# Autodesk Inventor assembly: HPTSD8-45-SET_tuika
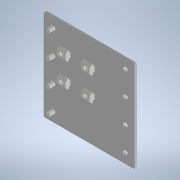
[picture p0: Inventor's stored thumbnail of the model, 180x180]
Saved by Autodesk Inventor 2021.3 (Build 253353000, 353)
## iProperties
Created: 2022-02
Part Number: HPTSD8-45-SET_tuika
Document SubType Name: Assembly
Designer: kengo
Author: kengo
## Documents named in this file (4)
- C:\Users\kengo\Documents\S2S_frame\SDC345\frame_misumi_ver12\HPTSD8-45-SET_tuika.iam
- C:\Users\kengo\Documents\S2S_frame\SDC345\frame_misumi_ver12\HNTT8-8.ipt
- C:\Users\kengo\Documents\S2S_frame\SDC345\frame_misumi_ver12\CBM8-15.ipt
- C:\Users\kengo\Documents\S2S_frame\SDC345\frame_misumi_ver12\JTACS-SUD-A170-B170-T4-X17_5-F45-Y17_5-G135-N8-L107_5-V45-S17_5-W135-NA8.ipt
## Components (9 placed, 3 different names)
1. HNTT8-8 — フラッシュ:1, フラッシュ:5
2. CBM8-15 — フラッシュ:5, リジッド:2
3. HNTT8-8:1 — フラッシュ:2, フラッシュ:6
4. CBM8-15:1 — フラッシュ:6, リジッド:4
5. HNTT8-8:2 — フラッシュ:1, フラッシュ:3
6. CBM8-15:2 — フラッシュ:3, リジッド:1
7. HNTT8-8:3 — フラッシュ:2, フラッシュ:4
8. CBM8-15:3 — フラッシュ:4, リジッド:3
9. JTACS-SUD-A170-B170-T4-X17_5-F45-Y17_5-G135-N8-L107_5-V45-S17_5-W135-NA8:1 — リジッド:1, リジッド:2, リジッド:3, リジッド:4
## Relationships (10: Flush 6, WeldJoint 4)
- フラッシュ:1 [Flush]: HNTT8-8 ↔ HNTT8-8:2
- フラッシュ:2 [Flush]: HNTT8-8:1 ↔ HNTT8-8:3
- フラッシュ:3 [Flush]: HNTT8-8:2 ↔ CBM8-15:2
- フラッシュ:4 [Flush]: HNTT8-8:3 ↔ CBM8-15:3
- フラッシュ:5 [Flush]: HNTT8-8 ↔ CBM8-15
- フラッシュ:6 [Flush]: HNTT8-8:1 ↔ CBM8-15:1
- リジッド:1 [WeldJoint]: CBM8-15:2 ↔ JTACS-SUD-A170-B170-T4-X17_5-F45-Y17_5-G135-N8-L107_5-V45-S17_5-W135-NA8:1
- リジッド:2 [WeldJoint]: CBM8-15 ↔ JTACS-SUD-A170-B170-T4-X17_5-F45-Y17_5-G135-N8-L107_5-V45-S17_5-W135-NA8:1
- リジッド:3 [WeldJoint]: CBM8-15:3 ↔ JTACS-SUD-A170-B170-T4-X17_5-F45-Y17_5-G135-N8-L107_5-V45-S17_5-W135-NA8:1
- リジッド:4 [WeldJoint]: CBM8-15:1 ↔ JTACS-SUD-A170-B170-T4-X17_5-F45-Y17_5-G135-N8-L107_5-V45-S17_5-W135-NA8:1
